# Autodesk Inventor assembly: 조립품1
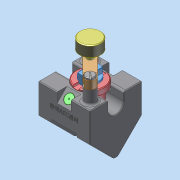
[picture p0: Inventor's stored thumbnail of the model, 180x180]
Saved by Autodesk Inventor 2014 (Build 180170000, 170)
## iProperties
Created: 2025-02
Part Number: 조립품1
Document SubType Name: Assembly
Designer: dg
Author: dg
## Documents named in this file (9)
- F:\조립품1.iam
- F:\부품1.ipt
- C:\Users\dg\Documents\Inventor\드릴부시.ipt
- F:\Imported Components\가공품\가공품.ipt
- F:\Imported Components\조\조.ipt
- F:\Imported Components\고정핀\고정핀.ipt
- F:\Imported Components\노브\노브.ipt
- F:\Imported Components\서포터\서포터.ipt
- F:\Imported Components\스트리퍼 볼트 M6x10\스트리퍼 볼트 M6x10.ipt
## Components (2 placed, 2 different names)
1. 가공품:1
2. 고정핀:1
